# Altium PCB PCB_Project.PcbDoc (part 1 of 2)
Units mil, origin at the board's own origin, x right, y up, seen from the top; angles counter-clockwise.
Board outline 8500 x 3000 mil, 2 copper layers (Top Layer, Bottom Layer), stack 62 mil thick; 123 components, 59 nets, 356 pads, 0 vias.
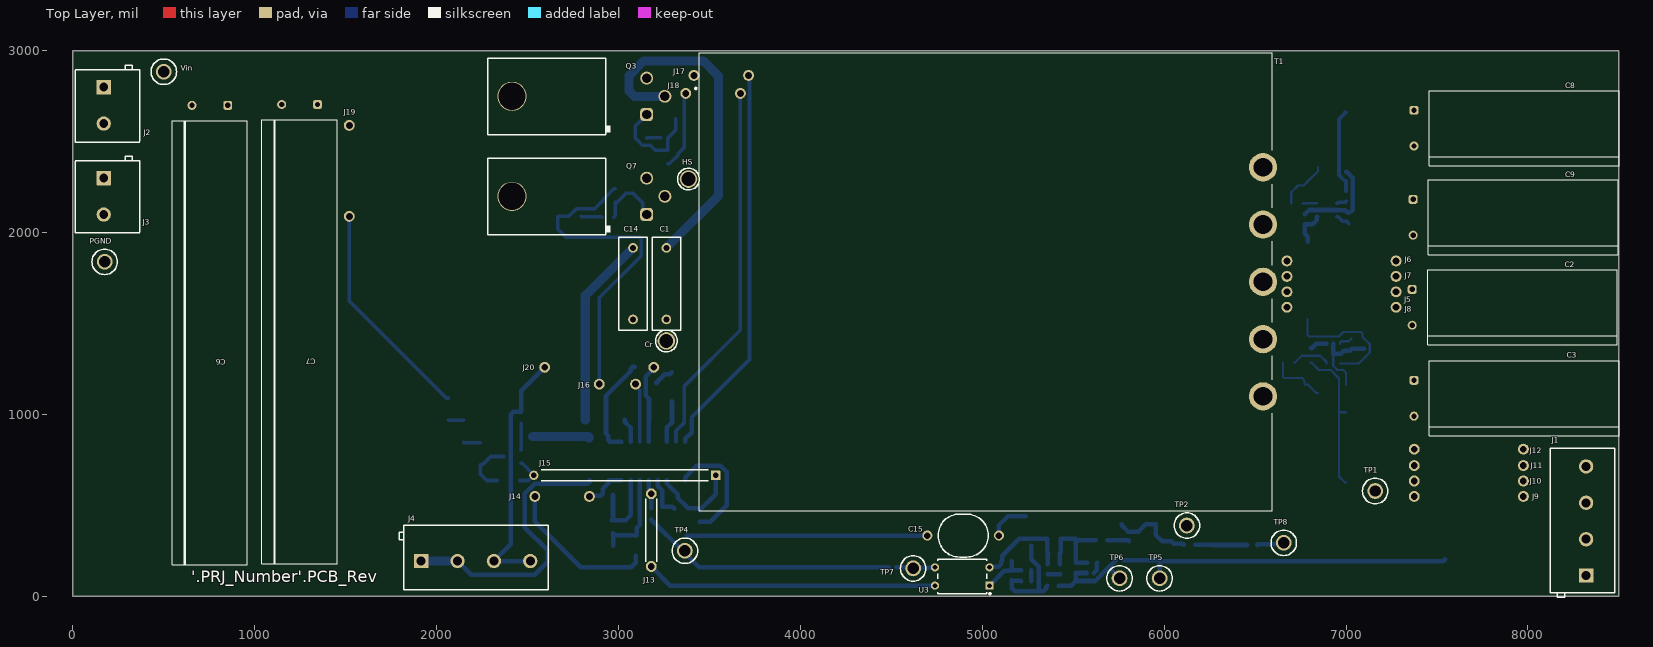
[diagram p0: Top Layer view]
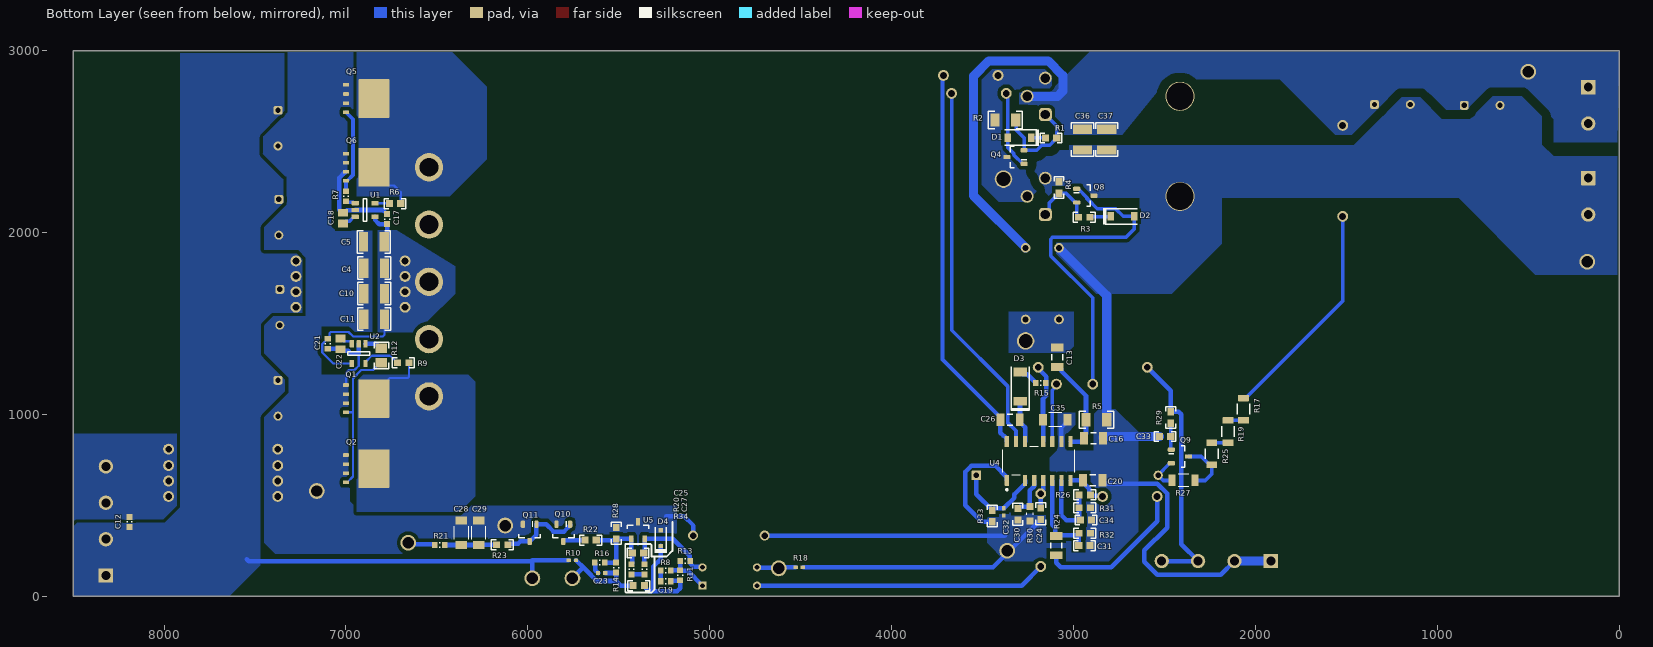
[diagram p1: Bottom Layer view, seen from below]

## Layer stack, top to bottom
Top Solder: solder mask 0.4, Solder Resist, Dk 3.5
Top Layer: signal copper 2.8
Dielectric1: core 56.4, FR-4 High Tg, Dk 4.8
Bottom Layer: signal copper 2.8
Bottom Solder: solder mask 0.4, Solder Resist, Dk 3.5

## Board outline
0,0 0,3000 8500,3000 8500,0

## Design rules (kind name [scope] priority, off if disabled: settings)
AcuteAngle [All] p1: minimum=4.50000000000000E+0001 checktracksonly=FALSE
AssemblyTestPointUsage [All] p1: valid=2
Clearance Clearance_2 [InNetClass('HV') vs Not InNetClass('HV')] p1: gap=50 ignorepadtopadclearanceinfootprint=FALSE except(0: Arc-Hole Track-Hole SMDPad-Hole THPad-Hole Via-Hole Fill-Hole Poly-Hole Region-Hole Text-Hole)
Clearance Clearance_1 [InNetClass('MV') vs Not InNetClass('MV')] p2: gap=20 ignorepadtopadclearanceinfootprint=FALSE
Clearance Clearance_Keepouts [((IsTrack Or IsArc) And Not InPoly) And IsFree and IsKeepOut vs ((IsTrack Or IsArc) And Not InPoly) And IsFree and IsKeepOut] p3: gap=0 ignorepadtopadclearanceinfootprint=FALSE
Clearance Clearance_BoardEdge_MountingHoles [OnCopper and InComponentClass('Mounting Holes') vs IsKeepOut] p4: gap=40 ignorepadtopadclearanceinfootprint=FALSE except(0: Arc-Hole Track-Hole SMDPad-Hole THPad-Hole Via-Hole Fill-Hole Poly-Hole Region-Hole Text-Hole)
Clearance Clearance_BoardEdge_Poly [OnCopper and InPoly vs IsKeepOut] p5: gap=25 ignorepadtopadclearanceinfootprint=FALSE except(0: Arc-Hole Track-Hole SMDPad-Hole THPad-Hole Via-Hole Fill-Hole Poly-Hole Region-Hole Text-Hole)
Clearance Clearance_BoardEdge [OnCopper and Not InComponentClass('Logo') and not InComponentClass('FiducialMark') and not InRegion(1000,500,4000,800) and Not IsKeepout vs IsKeepOut] p6: gap=75 ignorepadtopadclearanceinfootprint=FALSE except(0: Arc-Hole Track-Hole SMDPad-Hole THPad-Hole Via-Hole Fill-Hole Poly-Hole Region-Hole Text-Hole)
Clearance Clearance_Poly [InPolygon] p7: gap=20 ignorepadtopadclearanceinfootprint=FALSE except(0: Arc-Hole Track-Hole SMDPad-Hole THPad-Hole Via-Hole Fill-Hole Poly-Hole Region-Hole Text-Hole)
Clearance [All] p8: gap=7.87 ignorepadtopadclearanceinfootprint=FALSE except(0: Arc-Hole Track-Hole SMDPad-Hole THPad-Hole Via-Hole Fill-Hole Poly-Hole Region-Hole Text-Hole)
ComponentClearance ComponentClearance_MountingHoles_FiducialMarks [InComponentClass('Mounting Holes') vs InComponentClass('FiducialMark')] p1: gap=20 collisioncheckmode=3 verticalgap=10 showdistances=FALSE
ComponentClearance ComponentClearance_Shunt [InComponentClass('Header') vs InComponentClass('Shunt')] p2: gap=0 collisioncheckmode=3 verticalgap=0 showdistances=FALSE
ComponentClearance ComponentClearance_Logo [InComponentClass('Logo')] p3: gap=5 collisioncheckmode=3 verticalgap=10 showdistances=FALSE
ComponentClearance ComponentClearance_ScrewToNut [(HasFootprint('NY PMS 440 0025 PH')) vs (HasFootprint('Keystone_1902C'))] p4: gap=20 collisioncheckmode=3 verticalgap=100000 showdistances=FALSE
ComponentClearance ComponentClearance_MountingHoles [InComponentClass('Mounting Holes')] p5: gap=20 collisioncheckmode=3 verticalgap=10 showdistances=FALSE
ComponentClearance ComponentClearance_SmallPassives [HasFootprint('0201*') or HasFootprint('0402*') or HasFootprint('0508') or HasFootprint('0603*') or HasFootprint('0612') or HasFootprint('0805*') or HasFootprint('0815*') or HasFootprint('0830*') or HasFootprint('1206*') or HasFootprint('1210*') or HasFootprint('1808*') or HasFootprint('1812*') or HasFootprint('1825*') or HasFootprint('2010*') or HasFootprint('2220*') or HasFootprint('2225*') or HasFootprint('2512*') or HasFootprint('2728*') or HasFootprint('3518*') vs HasFootprint('0201*') or HasFootprint('0402*') or HasFootprint('0508') or HasFootprint('0603*') or HasFootprint('0612') or HasFootprint('0805*') or HasFootprint('0815*') or HasFootprint('0830*') or HasFootprint('1206*') or HasFootprint('1210*') or HasFootprint('1808*') or HasFootprint('1812*') or HasFootprint('1825*') or HasFootprint('2010*') or HasFootprint('2220*') or HasFootprint('2225*') or HasFootprint('2512*') or HasFootprint('2728*') or HasFootprint('3518*')] p6: gap=20 collisioncheckmode=3 verticalgap=20 showdistances=FALSE
ComponentClearance ComponentClearance_THtoSMT [IsThruComponent vs IsSMTComponent] p7: gap=10 collisioncheckmode=3 verticalgap=10 showdistances=FALSE
ComponentClearance ComponentClearance_THtoTH [IsThruComponent vs IsThruComponent] p8: gap=10 collisioncheckmode=3 verticalgap=10 showdistances=FALSE
ComponentClearance [All] p9: gap=10 collisioncheckmode=3 verticalgap=10 showdistances=FALSE
DiffPairsRouting [All] p1: maxlimit=100 minlimit=10 mostfreqgap=10 toplayer_minwidth=15 toplayer_maxwidth=15 toplayer_prefwidth=15 bottomlayer_minwidth=15 bottomlayer_maxwidth=15 bottomlayer_prefwidth=15 maxuncoupledlength=1000
FabricationTestPointUsage TestPointUsage [All] p1: valid=2 allowmultiple=FALSE
FabricationTestpoint Testpoint [All] p1: side=3 testpointundercomponent=TRUE minsize=40 maxsize=100 preferedsize=60 minholesize=0 maxholesize=40 preferedholesize=32 testpointgrid=1 allowsidetop=TRUE allowsidebottom=TRUE usegrid=TRUE gridtolerance=0.01
FanoutControl Fanout_LCC [IsLCC] p1: bgadir=Out bgaviamode=Centered fanoutstyle=Auto fanoutdirection=Alternating viagrid=1 // Fanout_LCC (Default Rule)
FanoutControl Fanout_BGA [IsBGA] p2: bgadir=Out bgaviamode=Centered fanoutstyle=Auto fanoutdirection=Alternating viagrid=1 // Fanout_BGA (Default Rule)
FanoutControl Fanout_Default [All] p4: bgadir=Out bgaviamode=Centered fanoutstyle=Auto fanoutdirection=Alternating viagrid=1 // Fanout_Default (Default Rule)
FanoutControl Fanout_Small [(CompPinCount < 5)] p5: bgadir=Out bgaviamode=Centered fanoutstyle=Auto fanoutdirection=OutThenIn viagrid=1 // Fanout_Small (Default Rule)
Height [All] p1: minheight=0 maxheight=3000 prefheight=500
HoleSize [All] p1: absolutevalues=TRUE maxlimit=251 minlimit=7 maxpercent=80.000 minpercent=20.000
MinimumAnnularRing MinimumAnnularRing_ThermalPadVias [IsVia and InAnyComponent] p1: minimumring=5.91
MinimumAnnularRing [All] p2: minimumring=4.9
MinimumSolderMaskSliver MinimumSolderMaskSliver_Logo [InComponentClass('Logo') vs InComponentClass('Logo')] p1: minsoldermaskwidth=0.7
MinimumSolderMaskSliver [All] p2: minsoldermaskwidth=2
PlaneConnect [All] p1: planeconnectstyle=Direct reliefexpansion=10 reliefentries=4 reliefconductorwidth=10 reliefairgap=10
PolygonConnect PolygonConnect_16 [All vs IsNamedPolygon('C106_2') Or  IsNamedPolygon('Vout') Or  IsNamedPolygon('IN+') Or  IsNamedPolygon('Q203_5') Or  IsNamedPolygon('IN+') Or  IsNamedPolygon('Q201_5') Or  IsNamedPolygon('C108_2') Or  IsNamedPolygon('SGND') Or  IsNamedPolygon('IN+') Or  IsNamedPolygon('SGND') Or  IsNamedPolygon('Q203_5') Or  IsNamedPolygon('IN+') Or  IsNamedPolygon('SGND') Or  IsNamedPolygon('GND') Or  IsNamedPolygon('C113_2') Or  IsNamedPolygon('C107_2') Or  IsNamedPolygon('C107_2') Or  IsNamedPolygon('Vout') Or  IsNamedPolygon('SIGNAL_LAYER_1_GND_P074') Or  IsNamedPolygon('HV') Or  IsNamedPolygon('C108_2') Or  IsNamedPolygon('C103_2') Or  IsNamedPolygon('Q201_5') Or  IsNamedPolygon('Vout') Or  IsNamedPolygon('C109_2') Or  IsNamedPolygon('Q201_5') Or  IsNamedPolygon('GND') Or  IsNamedPolygon('C107_2') Or  IsNamedPolygon('C102_1') Or  IsNamedPolygon('GND') Or  IsNamedPolygon('SGND') Or  IsNamedPolygon('HS') Or  IsNamedPolygon('Q203_5') Or  IsNamedPolygon('Q201_5') Or  IsNamedPolygon('Q203_5')] p1: connectstyle=Direct reliefconductorwidth=10 reliefentries=4 polygonreliefangle="90 Angle" airgapwidth=10
PolygonConnect PolygonConnect_15 [All vs IsNamedPolygon('C109_2') Or  IsNamedPolygon('C107_2') Or  IsNamedPolygon('HV') Or  IsNamedPolygon('Q203_5') Or  IsNamedPolygon('C107_2') Or  IsNamedPolygon('HS') Or  IsNamedPolygon('Q201_5') Or  IsNamedPolygon('Q203_5') Or  IsNamedPolygon('C106_2') Or  IsNamedPolygon('C108_2') Or  IsNamedPolygon('Vout') Or  IsNamedPolygon('Q203_5') Or  IsNamedPolygon('C108_2') Or  IsNamedPolygon('C113_2') Or  IsNamedPolygon('Q203_5') Or  IsNamedPolygon('Q201_5') Or  IsNamedPolygon('C107_2') Or  IsNamedPolygon('C102_1') Or  IsNamedPolygon('SGND') Or  IsNamedPolygon('GND') Or  IsNamedPolygon('SGND') Or  IsNamedPolygon('GND') Or  IsNamedPolygon('IN+') Or  IsNamedPolygon('IN+') Or  IsNamedPolygon('Q201_5') Or  IsNamedPolygon('Q201_5') Or  IsNamedPolygon('SGND') Or  IsNamedPolygon('SGND') Or  IsNamedPolygon('Vout') Or  IsNamedPolygon('Vout') Or  IsNamedPolygon('IN+') Or  IsNamedPolygon('GND') Or  IsNamedPolygon('IN+') Or  IsNamedPolygon('GND')] p2: connectstyle=Direct reliefconductorwidth=10 reliefentries=4 polygonreliefangle="90 Angle" airgapwidth=10
PolygonConnect PolygonConnect_14 [All vs IsNamedPolygon('C106_2') Or  IsNamedPolygon('C107_2') Or  IsNamedPolygon('C107_2') Or  IsNamedPolygon('C107_2') Or  IsNamedPolygon('C102_1') Or  IsNamedPolygon('Q203_5') Or  IsNamedPolygon('Vout') Or  IsNamedPolygon('Q203_5') Or  IsNamedPolygon('Q203_5') Or  IsNamedPolygon('Q201_5') Or  IsNamedPolygon('C108_2') Or  IsNamedPolygon('Q203_5') Or  IsNamedPolygon('HS') Or  IsNamedPolygon('HV') Or  IsNamedPolygon('C108_2') Or  IsNamedPolygon('Q201_5') Or  IsNamedPolygon('C109_2') Or  IsNamedPolygon('Q201_5') Or  IsNamedPolygon('Q201_5') Or  IsNamedPolygon('C113_2')] p3: connectstyle=Direct reliefconductorwidth=10 reliefentries=4 polygonreliefangle="90 Angle" airgapwidth=10
PolygonConnect PolygonConnect_13 [All vs IsNamedPolygon('C102_1') Or  IsNamedPolygon('HV') Or  IsNamedPolygon('C107_2') Or  IsNamedPolygon('C109_2') Or  IsNamedPolygon('C107_2') Or  IsNamedPolygon('C108_2') Or  IsNamedPolygon('C106_2') Or  IsNamedPolygon('C108_2') Or  IsNamedPolygon('C113_2') Or  IsNamedPolygon('C107_2')] p4: connectstyle=Direct reliefconductorwidth=10 reliefentries=4 polygonreliefangle="90 Angle" airgapwidth=10
PolygonConnect PolygonConnect_12 [All vs IsNamedPolygon('C107_2') Or  IsNamedPolygon('C113_2') Or  IsNamedPolygon('C106_2') Or  IsNamedPolygon('C107_2') Or  IsNamedPolygon('C107_2') Or  IsNamedPolygon('C102_1')] p5: connectstyle=Direct reliefconductorwidth=10 reliefentries=4 polygonreliefangle="90 Angle" airgapwidth=10
PolygonConnect PolygonConnect_11 [All vs IsNamedPolygon('C106_2') Or  IsNamedPolygon('C102_1') Or  IsNamedPolygon('C107_2') Or  IsNamedPolygon('C107_2') Or  IsNamedPolygon('C107_2')] p6: connectstyle=Direct reliefconductorwidth=10 reliefentries=4 polygonreliefangle="90 Angle" airgapwidth=10
PolygonConnect PolygonConnect_10 [All vs IsNamedPolygon('C106_2')] p7: connectstyle=Direct reliefconductorwidth=10 reliefentries=4 polygonreliefangle="90 Angle" airgapwidth=10
PolygonConnect PolygonConnect_9 [All vs IsNamedPolygon('C11_1') Or  IsNamedPolygon('Vin') Or  IsNamedPolygon('Vin') Or  IsNamedPolygon('5V') Or  IsNamedPolygon('D6_2') Or  IsNamedPolygon('Q3_3') Or  IsNamedPolygon('GND2') Or  IsNamedPolygon('GND2') Or  IsNamedPolygon('GND') Or  IsNamedPolygon('Q3_4') Or  IsNamedPolygon('12V5') Or  IsNamedPolygon('GND') Or  IsNamedPolygon('12V5') Or  IsNamedPolygon('D3_1')] p8: connectstyle=Direct reliefconductorwidth=10 reliefentries=4 polygonreliefangle="90 Angle" airgapwidth=10
PolygonConnect PolygonConnect_8 [All vs IsNamedPolygon('C11_1') Or  IsNamedPolygon('Vin') Or  IsNamedPolygon('12V5') Or  IsNamedPolygon('Q3_3') Or  IsNamedPolygon('GND2') Or  IsNamedPolygon('GND2') Or  IsNamedPolygon('5V') Or  IsNamedPolygon('Q3_4') Or  IsNamedPolygon('12V5')] p9: connectstyle=Direct reliefconductorwidth=10 reliefentries=4 polygonreliefangle="90 Angle" airgapwidth=10
PolygonConnect PolygonConnect_7 [All vs IsNamedPolygon('GND2') Or  IsNamedPolygon('GND2') Or  IsNamedPolygon('5V') Or  IsNamedPolygon('12V5') Or  IsNamedPolygon('12V5') Or  IsNamedPolygon('C11_1')] p10: connectstyle=Direct reliefconductorwidth=10 reliefentries=4 polygonreliefangle="90 Angle" airgapwidth=10
PolygonConnect PolygonConnect_6 [All vs IsNamedPolygon('GND2') Or  IsNamedPolygon('SGND') Or  IsNamedPolygon('GND1') Or  IsNamedPolygon('C901_1') Or  IsNamedPolygon('SGND') Or  IsNamedPolygon('GND2') Or  IsNamedPolygon('GND1')] p11: connectstyle=Direct reliefconductorwidth=10 reliefentries=4 polygonreliefangle="90 Angle" airgapwidth=10
PolygonConnect PolygonConnect_5 [All vs IsNamedPolygon('GND1') Or  IsNamedPolygon('GND1')] p12: connectstyle=Direct reliefconductorwidth=10 reliefentries=4 polygonreliefangle="90 Angle" airgapwidth=10
PolygonConnect PolygonConnect_4 [All vs IsNamedPolygon('C21_1') Or  IsNamedPolygon('C5_1') Or  IsNamedPolygon('C12_2') Or  IsNamedPolygon('C2_2') Or  IsNamedPolygon('C13_1') Or  IsNamedPolygon('C28_1') Or  IsNamedPolygon('C6_1') Or  IsNamedPolygon('GND') Or  IsNamedPolygon('GND2') Or  IsNamedPolygon('C14_1') Or  IsNamedPolygon('C13_1') Or  IsNamedPolygon('Q1_3') Or  IsNamedPolygon('C14_1') Or  IsNamedPolygon('C5_1') Or  IsNamedPolygon('GND2') Or  IsNamedPolygon('C28_1') Or  IsNamedPolygon('D5_2') Or  IsNamedPolygon('D6_2') Or  IsNamedPolygon('D2_1') Or  IsNamedPolygon('C12_2') Or  IsNamedPolygon('D2_1') Or  IsNamedPolygon('C4_1') Or  IsNamedPolygon('C4_1') Or  IsNamedPolygon('C2_2') Or  IsNamedPolygon('GND') Or  IsNamedPolygon('C33_1') Or  IsNamedPolygon('C9_1')] p13: connectstyle=Direct reliefconductorwidth=10 reliefentries=4 polygonreliefangle="90 Angle" airgapwidth=10
PolygonConnect PolygonConnect_3 [All vs IsNamedPolygon('C28_1') Or  IsNamedPolygon('C12_2') Or  IsNamedPolygon('C28_1') Or  IsNamedPolygon('C9_1') Or  IsNamedPolygon('D5_2') Or  IsNamedPolygon('C12_2') Or  IsNamedPolygon('C2_2') Or  IsNamedPolygon('C14_1') Or  IsNamedPolygon('C4_1') Or  IsNamedPolygon('C14_1') Or  IsNamedPolygon('D6_2') Or  IsNamedPolygon('GND2') Or  IsNamedPolygon('Q1_3') Or  IsNamedPolygon('C5_1') Or  IsNamedPolygon('D2_1') Or  IsNamedPolygon('C4_1') Or  IsNamedPolygon('C13_1') Or  IsNamedPolygon('C5_1') Or  IsNamedPolygon('C13_1') Or  IsNamedPolygon('C33_1') Or  IsNamedPolygon('D2_1') Or  IsNamedPolygon('GND') Or  IsNamedPolygon('GND') Or  IsNamedPolygon('GND2') Or  IsNamedPolygon('C2_2') Or  IsNamedPolygon('C6_1') Or  IsNamedPolygon('C21_1')] p14: connectstyle=Direct reliefconductorwidth=10 reliefentries=4 polygonreliefangle="90 Angle" airgapwidth=10
PolygonConnect PolygonConnect_2 [All vs IsNamedPolygon('C21_1') Or  IsNamedPolygon('C4_1') Or  IsNamedPolygon('D5_2') Or  IsNamedPolygon('C5_1') Or  IsNamedPolygon('C14_1') Or  IsNamedPolygon('C13_1') Or  IsNamedPolygon('C4_1') Or  IsNamedPolygon('C33_1') Or  IsNamedPolygon('C12_2') Or  IsNamedPolygon('D2_1') Or  IsNamedPolygon('C2_2') Or  IsNamedPolygon('C28_1') Or  IsNamedPolygon('C12_2') Or  IsNamedPolygon('D2_1') Or  IsNamedPolygon('C5_1') Or  IsNamedPolygon('Q1_3') Or  IsNamedPolygon('GND') Or  IsNamedPolygon('D6_2') Or  IsNamedPolygon('C6_1') Or  IsNamedPolygon('C2_2') Or  IsNamedPolygon('C14_1') Or  IsNamedPolygon('C28_1') Or  IsNamedPolygon('C13_1') Or  IsNamedPolygon('C9_1') Or  IsNamedPolygon('GND')] p15: connectstyle=Direct reliefconductorwidth=10 reliefentries=4 polygonreliefangle="90 Angle" airgapwidth=10
PolygonConnect PolygonConnect_1 [All vs IsNamedPolygon('C28_1') Or  IsNamedPolygon('D5_2') Or  IsNamedPolygon('C5_1') Or  IsNamedPolygon('C5_1') Or  IsNamedPolygon('D2_1') Or  IsNamedPolygon('C21_1') Or  IsNamedPolygon('C9_1') Or  IsNamedPolygon('C4_1') Or  IsNamedPolygon('C14_1') Or  IsNamedPolygon('C28_1') Or  IsNamedPolygon('C6_1') Or  IsNamedPolygon('C12_2') Or  IsNamedPolygon('C33_1') Or  IsNamedPolygon('C4_1') Or  IsNamedPolygon('C13_1') Or  IsNamedPolygon('C12_2') Or  IsNamedPolygon('D6_2') Or  IsNamedPolygon('C2_2') Or  IsNamedPolygon('C14_1') Or  IsNamedPolygon('D2_1') Or  IsNamedPolygon('C2_2') Or  IsNamedPolygon('C13_1')] p16: connectstyle=Direct reliefconductorwidth=10 reliefentries=4 polygonreliefangle="90 Angle" airgapwidth=10
PolygonConnect [All] p17: connectstyle=Direct reliefconductorwidth=10 reliefentries=4 polygonreliefangle="90 Angle" airgapwidth=10
RoutingVias ThermalPadVias [IsVia and InAnyComponent] p1: holewidth=7.87 width=19.68 viastyle="Through Hole" minholewidth=7.87 minwidth=19.68 maxholewidth=12.99 maxwidth=23.62
RoutingVias [All] p2: holewidth=16 width=34 viastyle="Through Hole" minholewidth=7.87 minwidth=20 maxholewidth=40 maxwidth=65
SilkToBoardRegionClearance [Not ((IsComment or IsDesignator) And (Hide <> 'False')) and not InRegion(1000,500,4000,800)] p1:
SilkToSilkClearance SilkToSilkClearance_Pb-FreeLogo [(HasFootprint('Pb-Free_Overlay_Medium') OR HasFootprint('Pb-Free_Overlay_Small')) vs (HasFootprint('Pb-Free_Overlay_Medium') OR HasFootprint('Pb-Free_Overlay_Small'))] p1: silktosilkclearance=0
SilkToSilkClearance [All] p2: silktosilkclearance=1
SilkToSolderMaskClearance "Silk to Solder Mask Opening" [All] p1: minsilkscreentomaskgap=1 clearancetoexposedcopper=FALSE
SolderMaskExpansion [All] p1: expansion=1.97 istentingtop=FALSE
Width [All] p1: maxlimit=100 minlimit=6 preferedwidth=10 checkconnectedcopper=TRUE
14 further rules are at their usual default settings.

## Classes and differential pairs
net class MV: NetR17_1 NetR19_1
net class HV: HO_BL HS_BL HVBUS NetC1_2 NetC26_1 NetD1_1 NetD1_2 NetHS_1 NetQ3_1

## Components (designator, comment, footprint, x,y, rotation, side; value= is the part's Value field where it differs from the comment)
C1 "PHE426MA5150JR05" PHE426_1300x400x900 3263.31,1720 r270 top value=0.015uF
C2 "EKZM350ELL681MJ25S" FP-EKZM350ELL681MJ25S_horizontalUp-MFG 7970,1590 r270 top value=680µF
C3 "EKZM350ELL681MJ25S" FP-EKZM350ELL681MJ25S_horizontalUp-MFG 7980,1090 r270 top value=680µF
C4 "GMK325BJ226MM-P" 1210 6845,1805 r180 bottom value=22uF
C5 "GMK325BJ226MM-P" 1210 6846.37,1950 r180 bottom value=22uF
C6 "450HXW82MEFR10X60" FP-450HXW82MEFR10X60_horizontalUp 753.43,1394.88 r180 top value=82µF
C7 "450HXW82MEFR10X60" FP-450HXW82MEFR10X60_horizontalUp 1246.57,1399.88 r180 top value=82µF
C8 "EKZM350ELL681MJ25S" FP-EKZM350ELL681MJ25S_horizontalUp-MFG 7980,2575 r270 top value=680µF
C9 "EKZM350ELL681MJ25S" FP-EKZM350ELL681MJ25S_horizontalUp-MFG 7975,2085 r270 top value=680µF
C10 "GMK325BJ226MM-P" 1210 6845.09,1665 r0 bottom value=22uF
C11 "GMK325BJ226MM-P" 1210 6845,1525 r0 bottom value=22uF
C12 "06035A101FAT2A" 0603L 8190,410 r90 bottom value=100pF
C13 "GRM31A5C2J151JW01D" 1206L 3088.6,1315 r270 bottom value=150pF
C14 "PHE426MA5150JR05" PHE426_1300x400x900 3080,1720 r90 top value=0.015uF
C15 "CD45-E2GA102M-NKA" CD45_700x600x1100 4895,335 r180 top value=1000pF
C16 "12061A101JAT2A" 1206L 2890,870.49 r180 bottom value=100pF
C17 "GRM188R71C105KE15D" 0603L 6773.37,2075 r90 bottom value=1uF
C18 "C2012X7R1V225K085AC" 0805L 7015,2080 r90 bottom value=2.2uF
C19 "C0603C472J1GAC7867" 0603L 5242.44,83.66 r0 bottom value=4700pF
C20 "C3216X7R1E475K085AB" 1206L 2893.94,638.7 r180 bottom value=4.7uF
C21 "GRM188R71C105KE15D" 0603L 7100,1390 r270 bottom value=1uF
C22 "C2012X7R1V225K085AC" 0805L 7030.22,1389.13 r270 bottom value=2.2uF
C23 "885012005062" 0402L 5594.25,129.03 r0 bottom value=150pF
C24 "C0603C332K5RACTU" 0603 3180,455 r270 bottom value=3300pF
C25 "06035A151JAT2A" 0603 5394.25,239.03 r180 bottom value=150pF
C26 "GRM31C5C1E104JA01L" 1206_180L 3348.74,971.51 r0 bottom value=0.1uF
C27 "06031C103JAT2A" 0603L 5359.25,149.03 r90 bottom value=0.01uF
C28 "C1206C106J3RACAUTO" 1206_180 6365,350 r90 bottom value=10uF
C29 "C1206C106J3RACAUTO" 1206_180 6270,350 r90 bottom value=10uF
C30 "C0603X222K5RACTU" 0603 3305.5,451.83 r270 bottom value=2200pF
C31 "C0603X221K5RACTU" 0603 2940,280 r180 bottom value=220pF
C32 "04025C102JAT2A" 0402L 3382.56,465 r270 bottom value=1000pF
C33 "C1608X7R2A102K080AA" 0603 2497.01,879.8 r0 bottom value=1000pF
C34 "C0603X221K5RACTU" 0603 2931.81,420.33 r180 bottom value=220pF
C35 "TMK316BBJ226ML-T" 1206_190 3100.75,971.51 r180 bottom value=22uF
C36 "GRM32QR72J223KW01L" 1210_150 2950.18,2512.04 r270 bottom value=0.022uF
C37 "GRM32QR72J223KW01L" 1210_150 2817.17,2512.04 r270 bottom value=0.022uF
Cr "0312-0-15-15-34-27-10-0" Mill-Max_0312-0-15-15-34-27-10-0 3263.31,1405 r90 top
D1 "PMEG3010EGWJ" SOD-123 3297.5,2522.77 r0 bottom value=30V
D2 "PMEG3010EGWJ" SOD-123 2730,2090 r180 bottom value=30V
D3 "ES1JAF" SMAF 3292.83,1153.5 r90 bottom value=600V
D4 "MM3Z15VST1G" SOD-323 5270,321.04 r90 bottom value=15V
HS "0312-0-15-15-34-27-10-0" Mill-Max_0312-0-15-15-34-27-10-0 3385,2295 r90 top
J1 "ED120/4DS" On-Shore_ED120_4DS 8320,415 r90 top
J2 "Receptacle_2x1" On-Shore_ED120_2DS 170,2700 r270 top
J3 "Receptacle_2x1" On-Shore_ED120_2DS 170,2200 r270 top
J4 "ED120/4DS" On-Shore_ED120_4DS 2215,195 r0 top
J5 "923345-06-C" CONN_923345-06-C 6975,1675 r0 top
J6 "923345-06-C" CONN_923345-06-C 6975,1845 r0 top
J7 "923345-06-C" CONN_923345-06-C 6975,1760 r0 top
J8 "923345-06-C" CONN_923345-06-C 6975,1590 r0 top
J9 "923345-06-C" CONN_923345-06-C 7675,550 r0 top
J10 "923345-06-C" CONN_923345-06-C 7675,635 r0 top
J11 "923345-06-C" CONN_923345-06-C 7675,720 r0 top
J12 "923345-06-C" CONN_923345-06-C 7675,810 r0 top
J13 "923345-04-C" 3M_923345-04-C 3180,365 r270 top
J14 "923345-03-C" 923345-03-C 2690,550 r0 top
J15 "923345-10-C" FP-923345-10-C_JUMPER2-MFG 3034.61,666.26 r180 top
J16 "923345-02-C" 923345-02-C 2994.12,1167.36 r180 top
J17 "923345-03-C" 923345-03-C 3565,2865 r180 top
J18 "923345-03-C" 923345-03-C 3520,2766.25 r180 top
J19 "923345-05-C" 923345-05-C 1520,2340 r90 top
J20 "923345-06-C" CONN_923345-06-C 2894.12,1260 r180 top
PGND "5011" Keystone5011 175,1840 r0 top
Q1 "CSD19532Q5B" DNK0008A 6888.94,1087.64 r180 bottom value=100V
Q2 "CSD19532Q5B" DNK0008A 6888.94,702.64 r180 bottom value=100V
Q3 "IPP60R099C7XKSA1" TO-220AB_Horizontal_100mil_Standoff2300 3155,2650 r90 top value=600V
Q4 "BC858C-7-F" SOT-23 3319.02,2416.11 r0 bottom value="30 V"
Q5 "CSD19532Q5B" DNK0008A 6888.94,2737.64 r180 bottom value=100V
Q6 "CSD19532Q5B" DNK0008A 6888.94,2360 r180 bottom value=100V
Q7 "IPP60R099C7XKSA1" TO-220AB_Horizontal_100mil_Standoff2300 3155,2100 r90 top value=600V
Q8 "BC858C-7-F" SOT-23 2935.19,2203.76 r180 bottom value="30 V"
Q9 "BSS127S-7" SOT-23 2415,770 r180 bottom value=600V
Q10 "MMBTA05LT1G" SOT-23 5805,350 r270 bottom value="60 V"
Q11 "MMBTA05LT1G" SOT-23 5990,350 r270 bottom value="60 V"
R1 "RC0603FR-0722R1L" 0603 3123.26,2520.74 r180 bottom value=22.1
R2 "CRCW120610K0FKEA" 1206 3375,2620 r180 bottom value=10.0k
R3 "RC0603FR-0722R1L" 0603 2941.5,2085 r0 bottom value=22.1
R4 "M55342K12B10E0T" 0603 3080,2248.87 r270 bottom value=10.0k
R5 "RC1206FR-07187RL" 1206 2874.25,971.51 r0 bottom value=187
R6 "RC0603FR-072KL" 0603 6730,2160 r180 bottom value=2.00k
R7 "RC0603JR-070RL" 0603L 6999.96,2200 r270 bottom value=0
R8 "RC0603FR-071K21L" 0603L 5242.44,143.66 r0 bottom value=1.21k
R9 "RC0603FR-072KL" 0603 6685,1285 r180 bottom value=2.00k
R10 "RC0402JR-070RL" 0402L 5755,200 r0 bottom value=0
R11 "RC0603FR-079K09L" 0603L 5162.44,117.16 r270 bottom value=9.09k
R12 "RC0805JR-070RL" 0805_HV 6805,1325 r270 bottom value=0
R13 "RC0603FR-072K05L" 0603L 5135,195 r0 bottom value=2.05k
R14 "RC0603FR-07147KL" 0603L 5514.25,159.03 r270 bottom value=147k
R15 "ERJ-3RQF2R2V" 0603L 3180,1174.25 r0 bottom value=2.20
R16 "ERJ-3EKF1002V" 0603L 5604.25,186.59 r0 bottom value=10.0k
R17 "KTR18EZPF3304" FP-KTR18EZPF3304_1206-MFG 2065,1030 r90 bottom
R18 "ERJ-2RKF1002X" 0402L 4507.58,160 r0 bottom value=10.0k
R19 "KTR18EZPF3304" FP-KTR18EZPF3304_1206-MFG 2150,907.28 r90 bottom
R20 "RC0603FR-0733K2L" 0603L 5429.25,149.03 r270 bottom value=33.2k
R21 "CRCW06031K00FKEA" 0603L 6485,283.07 r0 bottom value=1.00k
R22 "RC0603FR-0733K2L" 0603 5655,310 r180 bottom value=33.2k
R23 "RC0603FR-07100KL" 0603 6140,285 r0 bottom value=100k
R24 "CRCW12063M01FKEA" 1206L 3095,280 r270 bottom value=3.01Meg
R25 "KTR18EZPF3304" FP-KTR18EZPF3304_1206-MFG 2240,785 r90 bottom
R26 "CRCW0603100KFKEA" 0603 2938.19,558.42 r180 bottom value=100k
R27 "RMCF1206ZT0R00" FP-RMCF1206ZT0R00_1206-MFG 2395,638.01 r180 bottom value=0
R28 "RC0603FR-0711KL" 0603 5514.25,348.28 r270 bottom value=11.0k
R29 "RC0603FR-072KL" 0603 2465.51,984.31 r90 bottom value=2.00k
R30 "B57371V2474J060" FP-B57371V2474J060_0603-MFG 3239.68,454.78 r90 bottom value=470k
R31 "RC0603FR-0716K2L" 0603 2938.19,488.26 r0 bottom value=16.2k
R32 "RC0603FR-07249KL" 0603 2938.19,347.43 r0 bottom value=249k
R33 "RC0603FR-0735K7L" 0603 3446.99,442.71 r90 bottom value=35.7k
R34 "RMCF0603ZT0R00" 0603 5389.76,60 r0 bottom value=0
T1 "63204" FP-63204_PTH_XRMS_80MM0_64MM0-MFG 5020,1730 r0 top
TP1 "5011" Keystone5011 7160,580 r0 top
TP2 "5011" Keystone5011 6125,390 r0 top
TP4 "5011" Keystone5011 3365,251.46 r0 top
TP5 "5010" Keystone5010 5975,100 r0 top
TP6 "5013" Keystone5013 5755,100 r0 top
TP7 "5012" Keystone5012 4620,154.48 r0 top
TP8 "5012" Keystone5012 6657.5,295 r0 top
U1 "UCC24612-2DBVT" DBV0005A_N 6895,2125 r180 bottom
U2 "UCC24612-2DBVT" DBV0005A_N 6930,1335 r270 bottom
U3 "VO618A-3" DIP-4 4890,110 r180 top
U4 "UCC256603DDBR" DDB0014A-MFG 3191.26,745 r90 bottom
U5 "TLVH431ACDBZR" DBZ0003A_N 5394.25,364.03 r90 bottom
Vin "5010" Keystone5010 500,2885 r0 top (schematic designator VIN)

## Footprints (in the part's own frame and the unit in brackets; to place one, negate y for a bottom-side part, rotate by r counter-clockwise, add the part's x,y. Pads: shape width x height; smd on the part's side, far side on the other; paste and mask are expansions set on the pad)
3M_923345-04-C [mil] "Jumper Wire, 400 mil Spacing, Yellow, Pkg of 200"
  round 60 hole 38: 1(-200,0) 2(200,0)
  silkscreen extent -173,-31 173,31, body extent -215,-30 215,30, height 80
0402L [mm] "0402 from SM-752 data"
  rect 0.6x0.5 smd: 1(-0.5,0) 2(0.5,0)
  body extent -0.55,-0.3 0.55,0.3, height 0.6
0603 [mm] "0603 from SM-752 data"
  rect 1x0.95 smd: 1(-0.8,0) 2(0.8,0)
  silkscreen extent -1.52,-0.69 1.52,0.69, body extent -0.87,-0.47 0.87,0.47, height 1
0603L [mm] "0603 from SM-752 data"
  rect 0.8x0.85 smd: 1(-0.7,0) 2(0.7,0)
  silkscreen extent -0.07,-0.33 0.07,0.33, body extent -0.87,-0.47 0.87,0.47, height 1
0805_HV [mil] "0805 with 30mil clearance between pads"
  rect 50x63 smd: 1(-40,0) 2(40,0)
  silkscreen extent -74,-40 74,40, body extent -43,-29 43,29, height 57
0805L [mm] "0805 from SM-752 data"
  rect 1.1x1.4 smd: 1(-0.75,0) 2(0.75,0)
  body extent -1.1,-0.72 1.1,0.72, height 1.45
1206 [mm] "1206 from SM-752 data"
  rect 1.3x1.85 smd: 1(-1.45,0) 2(1.45,0)
  silkscreen extent -2.4,-1.21 2.4,1.21, body extent -1.7,-0.9 1.7,0.9, height 1.35
1206_180 [mm] "1206_180"
  rect 1.1x1.6 smd: 1(-1.7,0) 2(1.7,0)
  silkscreen extent -0.9,-1 0.9,1, body extent -1.75,-0.95 1.75,0.95, height 1.8
1206_180L [mm] "1206_180"
  rect 1.1x1.75 smd: 1(-1.35,0) 2(1.35,0)
  silkscreen extent -0.4,-0.77 0.4,0.77, body extent -1.75,-0.95 1.75,0.95, height 1.8
1206_190 [mm] "1206_190"
  rect 1.1x1.6 smd: 1(-1.7,0) 2(1.7,0)
  silkscreen extent -0.9,-1 0.9,1, body extent -1.75,-0.95 1.75,0.95, height 1.9
1206L [mm] "1206 from SM-752 data"
  rect 1.1x1.75 smd: 1(-1.35,0) 2(1.35,0)
  silkscreen extent -0.4,-0.77 0.4,0.77, body extent -1.7,-0.9 1.7,0.9, height 1.35
1210 [mm] "1210 from SM-752 data"
  rect 1.3x2.7 smd: 1(-1.45,0) 2(1.45,0)
  silkscreen extent -2.32,-1.57 2.32,1.57, body extent -1.7,-1.35 1.7,1.35, height 1.35
1210_150 [mm] "1210"
  rect 1.3x2.7 smd: 1(-1.45,0) 2(1.45,0)
  silkscreen extent -2.32,-1.57 2.32,1.57, body extent -1.7,-1.35 1.7,1.35, height 1.5
923345-02-C [mil] "Wire Jumper"
  round 60 hole 38: 1(-100,0) 2(100,0)
  body extent -113,-37 113,40, height 100
923345-03-C [mil] "Wire Jumper"
  round 60 hole 38: 1(-150,0) 2(150,0)
  body extent -163,-40 163,37, height 100
923345-05-C [mil] "Wire Jumper 500mil"
  round 60 hole 38: 1(-250,0) 2(250,0)
  body extent -263,-33 263,33, height 71
CD45_700x600x1100 [mm] "TH, 2-Leads, Dia 7mm, Pin Spacing 10 mm"
  round 1.4 hole 0.9: 1(-5,0) 2(5,0)
  silkscreen extent -3.5,-3 3.5,3, body extent -5.34,-3.02 5.34,3.02, height 11
CONN_923345-06-C [mil] "3M, Wire jumper, 600 mil lenght, Blue"
  round 60 hole 37: 1(-300,0) 2(300,0)
  body extent -313,-35 314,35, height 70
DBV0005A_N [mm] "SOT23, 5-Leads, Body 2.9x1.6mm, Pitch 0.95mm, Lead Span 2.8mm, IPC Medium Density"
  rrect17% 1x0.6 smd: 1(-1.375,0.95) 2(-1.375,0) 3(-1.375,-0.95) 4(1.375,-0.95) 5(1.375,0.95)
  silkscreen extent -0.25,-1.55 0.25,1.55, body extent -1.42,-1.46 1.42,1.46, height 1.09
DBZ0003A_N [mm] "SOT23, 3-Leads, Body 2.9x1.3mm, Pitch 0.95mm, Lead Span 2.4mm, IPC Medium Density"
  rrect17% 1x0.6 smd: 1(-1.2,0.95) 2(-1.2,-0.95) 3(1.2,0)
  silkscreen extent 0.2,-1.5 0.7,1.5, body extent -1.26,-1.46 1.26,1.46, height 0.98
DDB0014A-MFG [mm]
  rrect17% 1.55x0.6 smd paste+0 mask+0: 1(-2.7,4.445) 3(-2.7,1.905) 4(-2.7,0.635) 5(-2.7,-0.635) 6(-2.7,-1.905) 7(-2.7,-3.175) 8(-2.7,-4.445) 9(2.7,-4.445) 10(2.7,-3.175) 11(2.7,-1.905) 12(2.7,-0.635) 14(2.7,1.905) 15(2.7,3.175) 16(2.7,4.445)
  silkscreen extent -4.12,-5 2,5, body extent -3.01,-4.95 3.01,4.95, height 1.75
DIP-4 [mm] "DIP, 4-Leads, Body 6.86x4.83mm, Pitch 2.54mm"
  rect 1.15x1.15 hole 0.65: 1(-3.81,1.27)
  round 1.15 hole 0.65: 2(-3.81,-1.27) 3(3.81,-1.27) 4(3.81,1.27)
  silkscreen extent -4,-2.41 3.43,2.52, body extent -4.02,-2.41 4.02,2.41, height 5.59
DNK0008A [mm] "SON, 8-Leads, Body 5x6mm"
  rrect39% 0.86x0.51 smd paste-0.05 mask-0.05: 1(-2.82,1.905) 2(-2.82,0.635) 3(-2.82,-0.635) 4(-2.82,-1.905) 5(2.82,-1.905) 6(2.82,-0.635) 7(2.82,0.635) 8(2.82,1.905)
  rrect40% 0.25x0.555 on Bottom Solder: 9(-0.83,-2.372) 9(-0.83,2.372)
  rrect40% 0.25x0.555 on Bottom Paste: 9(-0.83,-2.372) 9(-0.83,2.372)
  rrect11% 0.95x1.13 on Bottom Paste: 9(-0.535,-1.33) 9(-0.535,0) 9(-0.535,1.33) 9(0.615,-1.33) 9(0.615,0) 9(0.615,1.33) 9(1.765,-1.33) 9(1.765,0) 9(1.765,1.33)
  rrect3% 3.58x4 on Bottom Solder: 9(0.75,0)
  rrect5% 4.34x5.4 smd paste-3 mask-3: 9(1.08,0)
  body extent -3.05,-2.55 3.05,2.55, height 1.06
FP-450HXW82MEFR10X60_horizontalUp [mm]
  round 1.25 hole 0.75 paste-1000 mask+0: 1(2.5,-33.15)
  rrect50% 1.25x1.25 hole 0.75 paste-1000 mask+0: 2(-2.5,-33.15)
  silkscreen extent -5.25,-31 5.25,31, body extent -5.35,-33.87 5.35,31.1, height 0.25
FP-63204_PTH_XRMS_80MM0_64MM0-MFG [mm]
  round 3.95 hole 2.6 paste-1000 mask+0: 7(38.7,-16) 8(38.7,-8) 9(38.7,0) 10(38.7,8) 11(38.7,16)
  silkscreen extent -40.62,-32 40,32, body extent -40.1,-32.1 40.78,32.1, height 0.25
FP-923345-10-C_JUMPER2-MFG [mm]
  rrect8% 1.3x1.3 hole 0.8 paste-1000 mask+0: 1(-12.7,0)
  round 1.3 hole 0.8 paste-1000 mask+0: 2(12.7,0)
  silkscreen extent -11.68,-0.76 11.68,0.76, body extent -13.45,-0.86 13.45,0.86, height 0.25
FP-B57371V2474J060_0603-MFG [mm]
  rrect10% 1x1 smd paste+0 mask+0: 1(-1,0) 2(1,0)
  silkscreen extent -0.13,-0.48 0.13,0.48, body extent -0.8,-0.4 0.8,0.4, height 0.9
FP-EKZM350ELL681MJ25S_horizontalUp-MFG [mm]
  round 1.25 hole 0.75 paste-1000 mask+0: 1(2.5,-15.4)
  rrect50% 1.25x1.25 hole 0.75 paste-1000 mask+0: 2(-2.5,-15.4)
  silkscreen extent -5.25,-13.25 5.25,13.25, body extent -5.35,-16.12 5.35,13.35, height 0.25
FP-KTR18EZPF3304_1206-MFG [mm]
  rrect11% 0.9x1.5 smd paste+0 mask+0: 1(-1.55,0) 2(1.55,0)
  silkscreen extent -0.72,-0.87 0.72,0.87, body extent -1.6,-0.8 1.6,0.8, height 0.65
FP-RMCF1206ZT0R00_1206-MFG [mm]
  rrect10% 1x1.6 smd paste+0 mask+0: 1(-1.6,0) 2(1.6,0)
  silkscreen extent -0.72,-0.87 0.72,0.87, body extent -1.6,-0.8 1.6,0.8, height 0.7
Keystone5010 [mil] "Keystone Multipurpose loops"
  round 87 hole 63: 1(0,0)
  silkscreen extent -70,-70 70,70, body extent -63,-63 63,62, height 319
Keystone5011 [mil] "Keystone Multipurpose loops"
  round 87 hole 63: 1(0,0)
  silkscreen extent -70,-70 70,70, body extent -63,-63 63,62, height 319
Keystone5012 [mil] "Keystone Multipurpose loops"
  round 87 hole 63: 1(0,0)
  silkscreen extent -70,-70 70,70, body extent -63,-63 63,62, height 319
Keystone5013 [mil] "Keystone Multipurpose loops"
  round 87 hole 63: 1(0,0)
  silkscreen extent -70,-70 70,70, body extent -63,-63 63,62, height 319
Mill-Max_0312-0-15-15-34-27-10-0 [mm] "Pin Receptacle, .032-.046\" .075\" Dia, Gold, TH"
  round 2.45 hole 1.905: 1(0,0)
  silkscreen extent -1.52,-1.52 1.52,1.52, body extent -1.15,-1.15 1.16,1.15, height 0.46
On-Shore_ED120_2DS [mm] "ONSHORE"
  rrect5% 2x2 hole 1.25: 1(-2.54,0)
  round 2 hole 1.25: 2(2.54,0)
  silkscreen extent -5.6,-4 5.12,5, body extent -5.78,-4 5.08,5, height 13
On-Shore_ED120_4DS [mm] "ONSHORE"
  rrect5% 2x2 hole 1.25: 1(-7.62,0)
  round 2 hole 1.25: 2(-2.54,0) 3(2.54,0) 4(7.62,0)
  silkscreen extent -10.68,-4 10.16,5, body extent -10.86,-4 10.16,5, height 13
PHE426_1300x400x900 [mm] "TH, 2-Leads, Body 13x4mm, Lead Spacing 10mm"
  round 1.35 hole 0.85: 1(-5,0) 2(5,0)
  silkscreen extent -6.5,-2 6.5,2, body extent -6.5,-2 6.5,2, height 9
SMAF [mm] "SMD, 2-Leads, Body 3.8x2.5mm"
  rect 1.24x1.89 smd: 1(-2.04,0) 2(2.04,0)
  silkscreen extent -3.4,-1.3 2.8,1.3, body extent -2.35,-1.25 2.35,1.25, height 1
SOD-123 [mm] "On Semi recommended land pattern"
  rect 0.915x1.22 smd: 1(-1.637,0) 2(1.637,0)
  silkscreen extent -2.74,-1.17 2.03,1.17, body extent -1.93,-0.9 1.93,0.9, height 1.35
SOD-323 [mm] "NXP recommended land pattern"
  rect 0.6x0.6 smd paste-0.05: 1(-1.1,0) 2(1.1,0)
  silkscreen extent -2.06,-0.86 1.53,0.86, body extent -1.3,-0.67 1.3,0.68, height 1.1
SOT-23 [mm] "SOT23, 3-Leads, Body 2.9x1.3mm, Pitch 0.95mm, Lead Span 2.5mm, IPC Medium Density"
  rrect50% 1x0.6 smd: 1(-1.2,0.95) 2(-1.2,-0.95) 3(1.2,0)
  silkscreen extent -1.62,-1.5 0.7,1.5, body extent -1.16,-1.45 1.21,1.45, height 1
TO-220AB_Horizontal_100mil_Standoff2300 [mm] "TH, 3-Leads, Body 10.67x9.4mm"
  rrect50% 1.8x1.8 hole 1.3: 1(0,0)
  round 1.8 hole 1.3: 2(2.54,-2.54) 3(5.08,0)
  silkscreen extent -2.8,5.08 7.87,22.22, body extent -2.79,-2.85 7.88,22.22, height 7.13

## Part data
C1 C14: library part CMP-0012541-3, "CAP, Film, 0.015 uF, 630 V, +/- 20%, TH", Cap_Case=13x4x9mm, Manufacturer=Kemet, Supplier Part Number 1=399-11726-ND, Tolerance_%=20%, Value1=Unknown, Value2=630V, ValueDisplayed=0.015uF
C2 C3 C8 C9: library part CMP-0001423-2, "Cap Aluminum Lytic 680uF 35V 20% (10 X 25mm) Radial 5mm 2250mA 10000h 105 Bulk", Digikey Part Number=565-3577-ND, Leakage Current=238uA, Manufacturer="United Chemi-Con", Mouser Part Number=661-EKZM350E681MJ25S, Operating Temperature Range="-40°C to +105°C", Tolerance_%=20%, ValueDisplayed=680uF
C4 C5 C10 C11: library part CMP-0085817-1, "CAP, CERM, 22 µF, 35 V,+/- 20%, X5R, 1210", Cap_Case=1210, Manufacturer="Taiyo Yuden", TempCo=X5R, Tolerance_%=20%, Value2=35V, ValueDisplayed=22µF
C6 C7: library part CMP-0120349-2, "82 µF 450 V Aluminum Electrolytic Capacitors Radial, Can 2000 Hrs @ 105°C", Digikey Part Number=1189-450HXW82MEFR10X60-ND, Leakage Current=576.28uA, Manufacturer=Rubycon, Mouser Part Number=232-450HXW82MEFR10X6, Operating Temperature Range="-40°C to +105°C", Tolerance_%=20%, ValueDisplayed=82uF
C12: library part CMP-0006762-4, "CAP, CERM, 100 pF, 50 V, +/- 1%, C0G/NP0, 0603", Cap_Case=0603, Manufacturer=AVX, Supplier Part Number 1=478-6202-1-ND, TempCo=C0G/NP0, Tolerance_%=1%, Value1=Unknown, Value2=50V, ValueDisplayed=100pF
C13: library part CMP-0008885-2, "CAP, CERM, 150 pF, 630 V, +/- 5%, C0G/NP0, 1206", Cap_Case=1206, Manufacturer=MuRata, Supplier Part Number 1=490-5274-1-ND, TempCo=C0G/NP0, Tolerance_%=5%, Value1=Unknown, Value2=630V, ValueDisplayed=150pF
C15: library part CMP-0009595-2, "CAP, CERM, 1000 pF,  V, +/- 20%, E, D7xT6mm", Cap_Case=7x6x11mm, Manufacturer=TDK, Supplier Part Number 1=445-174535-ND, TempCo=E, Tolerance_%=20%, Value1=Unknown, Value2=V, ValueDisplayed=1000pF
C16: library part CMP-0008462-2, "CAP, CERM, 100 pF, 100 V, +/- 5%, C0G/NP0, 1206", Cap_Case=1206, Manufacturer=AVX, Supplier Part Number 1=478-1444-1-ND, TempCo=C0G/NP0, Tolerance_%=5%, Value1="0.701 ohm", Value2=100V, ValueDisplayed=100pF
C17 C21: library part CMP-0007380-4, "CAP, CERM, 1 uF, 16 V, +/- 10%, X7R, 0603", Cap_Case=0603, Manufacturer=MuRata, Supplier Part Number 1=490-10734-1-ND, TempCo=X7R, Tolerance_%=10%, Value1=Unknown, Value2=16V, ValueDisplayed=1uF
C18 C22: library part CMP-0007883-2, "CAP, CERM, 2.2 uF, 35 V, +/- 10%, X7R, 0805", Cap_Case=0805, Manufacturer=TDK, Supplier Part Number 1=445-14547-1-ND, TempCo=X7R, Tolerance_%=10%, Value1=Unknown, Value2=35V, ValueDisplayed=2.2uF
C19: library part CMP-0006941-4, "CAP, CERM, 4700 pF, 100 V, +/- 5%, C0G/NP0, 0603", Cap_Case=0603, Manufacturer=Kemet, Supplier Part Number 1=399-9974-1-ND, TempCo=C0G/NP0, Tolerance_%=5%, Value1=Unknown, Value2=100V, ValueDisplayed=4700pF
C20: library part CMP-0008693-2, "CAP, CERM, 4.7 uF, 25 V, +/- 10%, X7R, 1206", Cap_Case=1206, Manufacturer=TDK, Supplier Part Number 1=445-14797-1-ND, TempCo=X7R, Tolerance_%=10%, Value1=Unknown, Value2=25V, ValueDisplayed=4.7uF
C23: library part CMP-0064913-2, "CAP, CERM, 150 pF, 50 V,+/- 5%, C0G/NP0, 0402", Cap_Case=0402, Manufacturer="Wurth Elektronik", Supplier Part Number 1=732-7476-1-ND, TempCo=C0G/NP0, Tolerance_%=5%, Value1=Unknown, Value2=50V, ValueDisplayed=150pF
C24: library part CMP-0006922-4, "CAP, CERM, 3300 pF, 50 V, +/- 10%, X7R, 0603", Cap_Case=0603, Manufacturer=Kemet, Supplier Part Number 1=399-1086-1-ND, TempCo=X7R, Tolerance_%=10%, Value1=Unknown, Value2=50V, ValueDisplayed=3300pF
C25: library part CMP-0006768-4, "CAP, CERM, 150 pF, 50 V, +/- 5%, C0G/NP0, 0603", Cap_Case=0603, Manufacturer=AVX, Supplier Part Number 1=478-1177-1-ND, TempCo=C0G/NP0, Tolerance_%=5%, Value1="0.098 ohm", Value2=50V, ValueDisplayed=150pF
C26: library part CMP-0064950-2, "CAP, CERM, 0.1 uF, 25 V,+/- 5%, C0G/NP0, 1206", Cap_Case=1206, Manufacturer=MuRata, Supplier Part Number 1=490-1767-1-ND, TempCo=C0G/NP0, Tolerance_%=5%, Value1=Unknown, Value2=25V, ValueDisplayed=0.1uF
C27: library part CMP-0006726-4, "CAP, CERM, 0.01 uF, 100 V, +/- 5%, X7R, 0603", Cap_Case=0603, Manufacturer=AVX, Supplier Part Number 1=478-3700-1-ND, TempCo=X7R, Tolerance_%=5%, Value1="0.098 ohm", Value2=100V, ValueDisplayed=0.01uF
C28 C29: library part CMP-0081062-1, "CAP, CERM, 10 µF, 25 V,+/- 5%, X7R, AEC-Q200 Grade 1, 1206", Cap_Case=1206_180, Manufacturer=Kemet, Supplier Part Number 1=399-15734-1-ND, TempCo=X7R, Tolerance_%=5%, Value2=25V, ValueDisplayed=10µF
C30: library part CMP-0006983-4, "CAP, CERM, 2200 pF, 50 V, +/- 10%, X7R, 0603", Cap_Case=0603, Manufacturer=Kemet, Supplier Part Number 1=399-5341-1-ND, TempCo=X7R, Tolerance_%=10%, Value1=Unknown, Value2=50V, ValueDisplayed=2200pF
C31 C34: library part CMP-0006982-4, "CAP, CERM, 220 pF, 50 V, +/- 10%, X7R, 0603", Cap_Case=0603, Manufacturer=Kemet, Supplier Part Number 1=399-5342-1-ND, TempCo=X7R, Tolerance_%=10%, Value1=Unknown, Value2=50V, ValueDisplayed=220pF
C32: library part CMP-0861060-1, "CAP, CERM, 1000 pF, 50 V,+/- 5%, X7R, 0402", Cap_Case=0402, Manufacturer=AVX, TempCo=X7R, Tolerance_%=5%, Value2=50V, ValueDisplayed=1000pF
C33: library part CMP-0007053-4, "CAP, CERM, 1000 pF, 100 V, +/- 10%, X7R, 0603", Cap_Case=0603, Manufacturer=TDK, Supplier Part Number 1=445-1298-1-ND, TempCo=X7R, Tolerance_%=10%, Value1=Unknown, Value2=100V, ValueDisplayed=1000pF
C35: library part CMP-0009024-2, "CAP, CERM, 22 uF, 25 V, +/- 20%, X5R, 1206_190", Cap_Case=1206, Manufacturer="Taiyo Yuden", Supplier Part Number 1=587-3246-1-ND, TempCo=X5R, Tolerance_%=20%, Value1=Unknown, Value2=25V, ValueDisplayed=22uF
C36 C37: library part CMP-0009248-2, "CAP, CERM, 0.022 uF, 630 V, +/- 10%, X7R, 1210", Cap_Case=1210, Manufacturer=MuRata, Supplier Part Number 1=490-3514-1-ND, TempCo=X7R, Tolerance_%=10%, Value1=Unknown, Value2=630V, ValueDisplayed=0.022uF
Cr HS: library part CMP-0055026-1, "Pin Receptacle, .032-.046\" .075\" Dia, Gold, TH", Manufacturer=Mill-Max, Supplier Part Number 1=0312-015153427100-ND
D1 D2: library part CMP-0079240-2, "Diode, Schottky, 30 V, 1 A, AEC-Q101, SOD-123", Manufacturer=Nexperia, Value1=1A, Value2=0.56V
D3: library part CMP-0029162-2, "Diode, Ultrafast, 600 V, 1 A, AEC-Q101, SMAF", Manufacturer="Fairchild Semiconductor", Value1=1A, Value2=1.7V
D4: library part CMP-0085762-1, "Diode, Zener, 15 V, 300 mW, SOD-323", Manufacturer="ON Semiconductor", Power_W=300mW, Value1=0.3W
J1 J4: library part CMP-0074939-1, "Terminal Block, 5.08 mm, 4x1, Brass, TH", Color=Blue, Current_A=15A, Manufacturer="On-Shore Technology", Supplier Part Number 1=ED2227-ND, Voltage_V=300V
J2 J3: library part CMP-0074910-1, "Terminal Block, 5.08 mm, 2x1, Brass, TH", Color=Blue, Current_A=15A, Manufacturer="On-Shore Technology", PartNumber=ED120/2DS, Supplier Part Number 1=ED1609-ND, Voltage_V=300V
J5 J6 J7 J8 J9 J10 J11 J12 J20: library part CMP-0074937-1, "Jumper Wire, 600mil spacing, Blue, pkg of 150, TH", Manufacturer=3M, Supplier Part Number 1=923345-06-ND
J13: library part CMP-0075057-1, "Jumper Wire, 400 mil Spacing, Yellow, Pkg of 200", Manufacturer=3M, Supplier Part Number 1=923345-04-ND
J14 J17 J18: library part CMP-0055440-1, "Jumper Wire, 300mil spacing, Orange, pkg of 200", Manufacturer=3M, Supplier Part Number 1=923345-03-ND
J15: library part CMP-0086742-1, "Jumper Wire Pre-Formed for Breadboard 1.000\" (25.40mm) 22 AWG 100 per Pkg", Manufacturer=3M
J16: library part CMP-0055439-1, "Jumper Wire, 200mil spacing, Red, pkg of 200", Manufacturer=3M, Supplier Part Number 1=923345-02-ND
J19: library part CMP-0055441-1, "Jumper Wire, 500mil spacing, Green, pkg of 200", Manufacturer=3M, Supplier Part Number 1=923345-05-ND
PGND TP1 TP2 TP4: library part CMP-0055148-2, "Test Point, Multipurpose, Black, TH", Color=Black, Manufacturer="Keystone Electronics", Supplier Part Number 1=36-5011-ND
Q1 Q2 Q5 Q6: library part CMP-0000958-3, "MOSFET, N-CH, 100 V, 17 A, DNK0008A (VSON-CLIP-8)", Alternate Manufacturer=None, Manufacturer="Texas Instruments", Supplier Part Number 1=296-37478-6-ND, Value2="48 nC"
Q3 Q7: library part CMP-0001171-3, "MOSFET, N-CH, 600 V, 22 A, TO-220AB", Alternate Manufacturer=None, Manufacturer="Infineon Technologies", Supplier Part Number 1=IPP60R099C7XKSA1-ND, Value2="42 nC"
Q4 Q8: library part CMP-0000317-2, "Transistor, PNP, 30 V, 0.1 A, SOT-23", Manufacturer="Diodes Inc.", Supplier Part Number 1=BC858C-7-F-ND, Value1="0.1 A", Value2=600
Q9: library part CMP-0001149-3, "MOSFET, N-CH, 600 V, 0.05 A, SOT-23", Alternate Manufacturer=None, Manufacturer="Diodes Inc.", Supplier Part Number 1=BSS127S-7DICT-ND, Value2="1.08 nC"
Q10 Q11: library part CMP-0000488-2, "Transistor, NPN, 60 V, 0.5 A, AEC-Q101, SOT-23", Manufacturer="ON Semiconductor", Supplier Part Number 1=MMBTA05LT1GOSCT-ND, Value1="0.5 A"
R1 R3: library part CMP-0022926-4, "RES, 22.1, 1%, 0.1 W, 0603", Manufacturer=Yageo, Power_W=100mW, Supplier Part Number 1=311-22.1HRCT-ND, TempCo="100 ppm/C", Tolerance_%=1%, Value2=0.1W, Value_Code=22R1, ValueDisplayed=22.1
R2: library part CMP-0016577-3, "RES, 10.0 k, 1%, 0.25 W, AEC-Q200 Grade 0, 1206", Manufacturer=Vishay-Dale, Power_W=250mW, Supplier Part Number 1=541-10.0KFCT-ND, TempCo="100 ppm/C", Tolerance_%=1%, Value2=0.25W, Value_Code=10k0, ValueDisplayed=10.0k
R4: library part CMP-0080488-1, "RES, 10.0 k, 1%, 0.1 W, 0603", Manufacturer="TT Electronics/IRC", Power_W=100mW, TempCo="100 ppm/C", Tolerance_%=1%, Value2=0.1W, Value_Code=10k0, ValueDisplayed=10.0k
R5: library part CMP-0017949-2, "RES, 187, 1%, 0.25 W, 1206", Manufacturer="Yageo America", Power_W=250mW, Supplier Part Number 1=311-187FRCT-ND, TempCo="100 ppm/C", Tolerance_%=1%, Value2=0.25W, Value_Code=187R, ValueDisplayed=187
R6 R9 R29: library part CMP-0023000-5, "RES, 2.00 k, 1%, 0.1 W, 0603", Manufacturer=Yageo, Power_W=100mW, Supplier Part Number 1=311-2.00KHRCT-ND, TempCo="100 ppm/C", Tolerance_%=1%, Value2=0.1W, Value_Code=2k00, ValueDisplayed=2.00k
R7: library part CMP-0025885-5, "RES, 0, 5%, 0.1 W, 0603", Manufacturer=Yageo, Power_W=100mW, Supplier Part Number 1=311-0.0GRCT-ND, TempCo="200 ppm/C", Tolerance_%=5%, Value2=0.1W, Value_Code=0000, ValueDisplayed=0
R8: library part CMP-0022871-5, "RES, 1.21 k, 1%, 0.1 W, 0603", Manufacturer=Yageo, Power_W=100mW, Supplier Part Number 1=311-1.21KHRCT-ND, TempCo="100 ppm/C", Tolerance_%=1%, Value2=0.1W, Value_Code=1k21, ValueDisplayed=1.21k
R10: library part CMP-0027004-2, "RES, 0, 5%, 0.063 W, 0402", Manufacturer="Yageo America", Power_W=63mW, Supplier Part Number 1=311-0.0JRCT-ND, TempCo="200 ppm/C", Tolerance_%=5%, Value2=0.063W, Value_Code=0000, ValueDisplayed=0
R11: library part CMP-0023332-5, "RES, 9.09 k, 1%, 0.1 W, 0603", Manufacturer=Yageo, Power_W=100mW, Supplier Part Number 1=311-9.09KHRCT-ND, TempCo="100 ppm/C", Tolerance_%=1%, Value2=0.1W, Value_Code=9k09, ValueDisplayed=9.09k
R12: library part CMP-0020803-2, "RES, 0, 5%, 0.125 W, 0805", Manufacturer="Yageo America", Power_W=125mW, Supplier Part Number 1=311-0.0ARCT-ND, TempCo="200 ppm/C", Tolerance_%=5%, Value2=0.125W, Value_Code=0000, ValueDisplayed=0
R13: library part CMP-0022981-5, "RES, 2.05 k, 1%, 0.1 W, 0603", Manufacturer=Yageo, Power_W=100mW, Supplier Part Number 1=311-2.05KHRCT-ND, TempCo="100 ppm/C", Tolerance_%=1%, Value2=0.1W, Value_Code=2k05, ValueDisplayed=2.05k
R14: library part CMP-0022800-4, "RES, 147 k, 1%, 0.1 W, 0603", Manufacturer=Yageo, Power_W=100mW, Supplier Part Number 1=311-147KHRCT-ND, TempCo="100 ppm/C", Tolerance_%=1%, Value2=0.1W, Value_Code=147k
R15: library part CMP-0022711-2, "RES, 2.20, 1%, 0.1 W, 0603", Manufacturer=Panasonic, Power_W=100mW, Supplier Part Number 1=P2.2AJCT-ND, TempCo="200 ppm/C", Tolerance_%=1%, Value2=0.1W, Value_Code=2R20, ValueDisplayed=2.20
